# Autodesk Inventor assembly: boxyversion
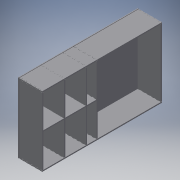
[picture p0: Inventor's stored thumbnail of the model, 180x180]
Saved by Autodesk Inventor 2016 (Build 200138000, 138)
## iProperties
Created: 2017-03
Part Number: boxyversion
Document SubType Name: Assembly
Designer: Corey
Author: Corey
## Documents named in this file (7)
- C:\Users\Corey\Dropbox\Files for Fab Academy\Week7\boxyversion.iam
- C:\Users\Corey\Dropbox\Files for Fab Academy\Week7\straightside.ipt
- C:\Users\Corey\Dropbox\Files for Fab Academy\Week7\shelf1.ipt
- C:\Users\Corey\Dropbox\Files for Fab Academy\Week7\midshelf.ipt
- C:\Users\Corey\Dropbox\Files for Fab Academy\Week7\centersupport.ipt
- C:\Users\Corey\Dropbox\Files for Fab Academy\Week7\topshelf.ipt
- C:\Users\Corey\Dropbox\Files for Fab Academy\Week7\backwall.ipt
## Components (9 placed, 6 different names)
1. straightside:1 — Rigid:1, Rigid:2
2. shelf1:1 — Rigid:1, Rigid:8
3. shelf1:2 — Rigid:2, Rigid:3, Rigid:6
4. straightside:2 — Rigid:3, Rigid:4, Rigid:5, Rigid:7
5. midshelf:1 — Rigid:4
6. midshelf:2 — Rigid:5
7. centersupport:1 — Rigid:6
8. topshelf:1 — Rigid:7
9. backwall:1 — Rigid:8
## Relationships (8: WeldJoint 8)
- Rigid:1 [WeldJoint]: straightside:1 ↔ shelf1:1
- Rigid:2 [WeldJoint]: straightside:1 ↔ shelf1:2
- Rigid:3 [WeldJoint]: shelf1:2 ↔ straightside:2
- Rigid:4 [WeldJoint]: straightside:2 ↔ midshelf:1
- Rigid:5 [WeldJoint]: straightside:2 ↔ midshelf:2
- Rigid:6 [WeldJoint]: shelf1:2 ↔ centersupport:1
- Rigid:7 [WeldJoint]: straightside:2 ↔ topshelf:1
- Rigid:8 [WeldJoint]: shelf1:1 ↔ backwall:1
## Named parameters: thick = 18.034 mm, top = 152.4 mm, bit = 6.35 mm, depth = 425.45 mm, height = 1917.7 mm, width = 1117.6 mm, panel = 368.3 mm, shoe = 152.4 mm, sweater = 330.2 mm, osb = 19.05 mm
